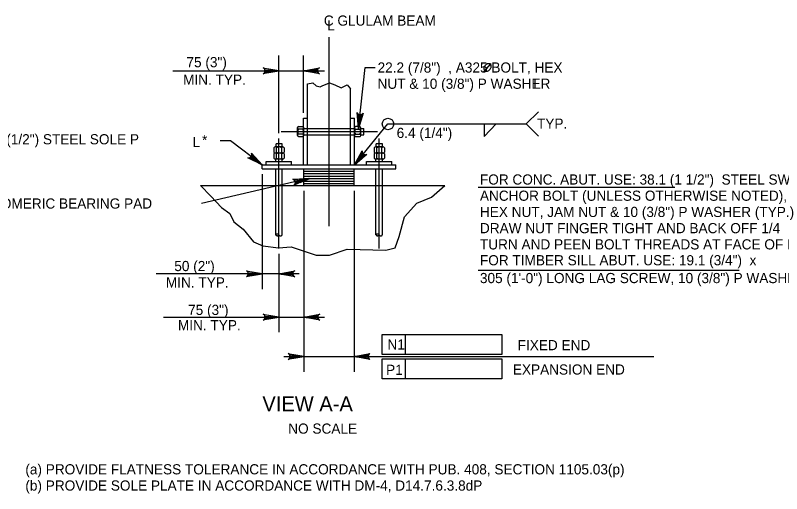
# Model space of a CAD drawing. Extents: x 638263 to 640360, y 293683 to 298655.
# Drawn here: x 638721.5 to 638947.3, y 293868.3 to 294009.4 of the extents above; entities that cross this region are included whole.
import ezdxf

# ---------------------------------------------------------------- set-up
doc = ezdxf.new("R2010")
doc.units = 0
doc.layers.add('3', color=7, linetype='Continuous')
doc.layers.add('4', color=7, linetype='Continuous')

msp = doc.modelspace()

# ---------------------------------------------------------------- linework, layer by layer
at = {"layer": '3'}
for p, q in [((638813.97, 293947.17), (638813.97, 294002.92)), ((638807.64, 293965.26), (638807.64, 293989.18)), ((638820.3, 293965.26), (638820.3, 293987.65)), ((638806.46, 293979.04), (638807.64, 293979.04)), ((638806.46, 293965.26), (638806.46, 293979.04)), ((638820.3, 293979.04), (638821.48, 293979.04)), ((638821.48, 293965.26), (638821.48, 293979.04)), ((638804.96, 293976.61), (638806.25, 293976.61)), ((638823.04, 293976.57), (638821.75, 293976.57)), ((638799.85, 293975.1), (638828.29, 293975.1)), ((638804.69, 293973.97), (638804.7, 293976.24)), ((638806.24, 293974.33), (638804.95, 293974.34)), ((638806.25, 293975.83), (638804.96, 293975.84)), ((638806.5, 293973.96), (638806.51, 293976.23)), ((638806.51, 293976.03), (638821.48, 293976.03)), ((638806.51, 293974.16), (638821.48, 293974.16)), ((638821.48, 293973.92), (638821.48, 293976.2)), ((638821.74, 293974.29), (638823.03, 293974.29)), ((638821.75, 293975.79), (638823.03, 293975.79)), ((638823.3, 293973.92), (638823.3, 293976.19)), ((638823.3, 293975.96), (638824.2, 293975.96)), ((638823.3, 293974.12), (638824.2, 293974.12)), ((638824.2, 293974.12), (638824.2, 293975.96)), ((638799.21, 293940.6), (638799.21, 293973.03)), ((638804.95, 293973.62), (638806.24, 293973.61)), ((638823.03, 293973.57), (638821.74, 293973.57)), ((638828.74, 293940.6), (638828.74, 293973.03)), ((638797.75, 293970.32), (638797.74, 293969.03)), ((638800.4, 293970.58), (638798.12, 293970.58)), ((638800.2, 293971.48), (638798.35, 293971.49)), ((638798.35, 293970.58), (638798.35, 293971.49)), ((638798.52, 293969.03), (638798.52, 293970.32)), ((638800.02, 293969.03), (638800.02, 293970.31)), ((638800.2, 293970.58), (638800.2, 293971.48)), ((638800.75, 293970.31), (638800.74, 293969.03)), ((638827.28, 293970.32), (638827.27, 293969.03)), ((638829.93, 293970.58), (638827.65, 293970.58)), ((638829.73, 293971.48), (638827.88, 293971.49)), ((638827.88, 293970.58), (638827.88, 293971.49)), ((638828.05, 293969.03), (638828.05, 293970.32)), ((638829.55, 293969.03), (638829.55, 293970.31)), ((638829.72, 293970.58), (638829.73, 293971.48)), ((638830.27, 293970.31), (638830.27, 293969.03)), ((638797.74, 293968.5), (638797.74, 293967.22)), ((638800.39, 293968.76), (638798.12, 293968.77)), ((638798.52, 293967.22), (638798.52, 293968.5)), ((638800.02, 293967.21), (638800.02, 293968.5)), ((638800.74, 293968.5), (638800.74, 293967.21)), ((638827.27, 293968.5), (638827.27, 293967.22)), ((638829.92, 293968.76), (638827.65, 293968.77)), ((638828.04, 293967.22), (638828.05, 293968.5)), ((638829.54, 293967.21), (638829.55, 293968.5)), ((638830.27, 293968.5), (638830.27, 293967.21)), ((638794.29, 293964.08), (638794.29, 293965.26)), ((638794.29, 293965.26), (638833.66, 293965.26)), ((638795.47, 293965.26), (638795.47, 293966.24)), ((638795.47, 293966.24), (638802.95, 293966.24)), ((638800.39, 293966.95), (638798.11, 293966.95)), ((638798.28, 293966.24), (638798.28, 293966.95)), ((638800.15, 293966.24), (638800.15, 293966.95)), ((638802.95, 293965.26), (638802.95, 293966.24)), ((638824.99, 293966.24), (638832.48, 293966.24)), ((638824.99, 293965.26), (638824.99, 293966.24)), ((638829.92, 293966.95), (638827.64, 293966.95)), ((638827.81, 293966.24), (638827.81, 293966.95)), ((638829.68, 293966.24), (638829.68, 293966.95)), ((638832.48, 293965.26), (638832.48, 293966.24)), ((638833.66, 293964.08), (638833.66, 293965.26)), ((638794.29, 293964.08), (638833.66, 293964.08)), ((638798.28, 293959.16), (638798.28, 293964.08)), ((638800.15, 293959.16), (638800.15, 293964.08)), ((638806.59, 293959.16), (638806.59, 293964.08)), ((638806.59, 293963.44), (638813.97, 293963.44)), ((638813.97, 293963.44), (638821.35, 293963.44)), ((638821.35, 293959.16), (638821.35, 293964.08)), ((638827.81, 293959.16), (638827.81, 293964.08)), ((638829.68, 293959.16), (638829.68, 293964.08)), ((638806.59, 293962.71), (638813.97, 293962.71)), ((638806.59, 293961.97), (638813.97, 293961.97)), ((638806.59, 293961.23), (638813.97, 293961.23)), ((638813.97, 293962.71), (638821.35, 293962.71)), ((638813.97, 293961.97), (638821.35, 293961.97)), ((638813.97, 293961.23), (638821.35, 293961.23)), ((638776.13, 293959.16), (638848.14, 293959.16)), ((638798.28, 293944.63), (638798.28, 293959.16)), ((638800.15, 293944.63), (638800.15, 293959.16)), ((638806.59, 293960.49), (638813.97, 293960.49)), ((638806.59, 293959.76), (638813.97, 293959.76)), ((638813.97, 293960.49), (638821.35, 293960.49)), ((638813.97, 293959.76), (638821.35, 293959.76)), ((638827.81, 293944.63), (638827.81, 293959.16)), ((638829.68, 293944.63), (638829.68, 293959.16))]:
    msp.add_line(p, q, dxfattribs=at)
for points in [[(638807.64, 293989.18), (638809.22, 293989.48), (638810.14, 293988.56), (638811.37, 293988.26), (638811.98, 293988.56), (638814.13, 293989.48), (638815.66, 293988.87), (638817.5, 293987.95), (638819.33, 293988.87), (638820.3, 293987.65)], [(638794.29, 293965.26), (638790.04, 293967.37), (638790.48, 293967.35), (638790.81, 293967.49), (638791.04, 293967.71), (638791.19, 293967.99), (638791.23, 293968.35), (638791.09, 293968.77), (638794.29, 293965.26), (638791.23, 293968.35), (638791.19, 293967.99), (638794.29, 293965.26), (638791.04, 293967.71), (638790.81, 293967.49), (638794.29, 293965.26), (638790.48, 293967.35)], [(638808.02, 293961.23), (638803.68, 293959.32), (638803.97, 293959.65), (638804.08, 293959.99), (638804.06, 293960.31), (638803.94, 293960.6), (638803.69, 293960.86), (638803.28, 293961.02), (638808.02, 293961.23), (638803.69, 293960.86), (638803.94, 293960.6), (638808.02, 293961.23), (638804.06, 293960.31), (638804.08, 293959.99), (638808.02, 293961.23), (638803.97, 293959.65)], [(638776.13, 293959.16), (638779.19, 293956.09), (638782.25, 293952.72), (638784.71, 293950.89), (638785.93, 293948.44), (638788.69, 293946.29), (638791.75, 293942.62), (638794.51, 293941.39), (638799.11, 293940.78), (638802.79, 293941.08), (638810.14, 293938.63), (638814.13, 293938.63), (638819.33, 293940.47), (638830.67, 293940.17), (638833.43, 293940.78), (638834.66, 293944.15), (638836.19, 293949.97), (638839.87, 293953.95), (638844.16, 293955.79), (638848.14, 293959.16)]]:
    msp.add_lwpolyline(points, dxfattribs=at)
for centre, radius, start, end in [((638805.11, 293976.23), 0.417, 111.1104, 181.6506), ((638806.1, 293976.22), 0.417, 357.9964, 68.5366), ((638821.9, 293976.18), 0.417, 111.1685, 181.7086), ((638822.88, 293976.18), 0.417, 358.0545, 68.5946), ((638805.89, 293975.09), 1.19, 140.8735, 218.7735), ((638805.07, 293973.98), 0.379, 107.2753, 252.3717), ((638805.11, 293976.23), 0.417, 181.6506, 248.5366), ((638805.32, 293975.09), 1.19, 320.8735, 38.7735), ((638806.13, 293973.98), 0.379, 287.2753, 72.3717), ((638806.1, 293976.22), 0.417, 291.1104, 357.9964), ((638821.9, 293976.18), 0.417, 181.7086, 248.5946), ((638822.67, 293975.04), 1.19, 140.9315, 218.8315), ((638821.86, 293973.93), 0.379, 107.3333, 252.4297), ((638822.88, 293976.18), 0.417, 291.1685, 358.0545), ((638822.11, 293975.04), 1.19, 320.9315, 38.8315), ((638822.92, 293973.93), 0.379, 287.3333, 72.4297), ((638798.14, 293970.17), 0.417, 88.0545, 158.5946), ((638798.14, 293970.17), 0.417, 21.1685, 88.0545), ((638799.27, 293969.39), 1.19, 50.9315, 128.8315), ((638800.38, 293970.2), 0.379, 17.3333, 162.4297), ((638827.66, 293970.17), 0.417, 88.0545, 158.5946), ((638827.66, 293970.17), 0.417, 21.1685, 88.0545), ((638828.8, 293969.39), 1.19, 50.9315, 128.8315), ((638829.91, 293970.2), 0.379, 17.3333, 162.4297), ((638798.13, 293969.19), 0.417, 201.1685, 271.7086), ((638798.13, 293968.35), 0.417, 88.0545, 158.5946), ((638798.13, 293968.35), 0.417, 21.1685, 88.0545), ((638799.27, 293969.96), 1.19, 230.9315, 308.8315), ((638799.27, 293967.57), 1.19, 50.9315, 128.8315), ((638800.38, 293969.14), 0.379, 197.3333, 342.4297), ((638800.38, 293968.39), 0.379, 17.3333, 162.4297), ((638827.66, 293969.19), 0.417, 201.1685, 271.7086), ((638827.66, 293968.35), 0.417, 88.0545, 158.5946), ((638827.66, 293969.19), 0.417, 271.7086, 338.5946), ((638827.66, 293968.35), 0.417, 21.1685, 88.0545), ((638828.8, 293969.96), 1.19, 230.9315, 308.8315), ((638828.8, 293967.57), 1.19, 50.9315, 128.8315), ((638829.91, 293969.14), 0.379, 197.3333, 342.4297), ((638829.91, 293968.39), 0.379, 17.3333, 162.4297), ((638798.13, 293967.37), 0.417, 201.1685, 271.7086), ((638798.13, 293967.37), 0.417, 271.7086, 338.5946), ((638799.27, 293968.14), 1.19, 230.9315, 308.8315), ((638800.38, 293967.33), 0.379, 197.3333, 342.4297), ((638827.66, 293967.37), 0.417, 201.1685, 271.7086), ((638827.66, 293967.37), 0.417, 271.7086, 338.5946), ((638828.8, 293968.14), 1.19, 230.9315, 308.8315), ((638829.91, 293967.33), 0.379, 197.3333, 342.4297), ((638798.58, 293944.51), 0.333, 117.9903, 142.0693), ((638798.68, 293944.32), 0.552, 102.4157, 117.9903), ((638798.75, 293944.01), 0.867, 90, 102.4157), ((638798.75, 293944.01), 0.867, 77.5843, 90), ((638798.81, 293944.32), 0.552, 62.0097, 77.5843), ((638798.92, 293944.51), 0.333, 37.9307, 62.0097), ((638828.1, 293944.51), 0.333, 117.9903, 142.0693), ((638828.21, 293944.32), 0.552, 102.4157, 117.9903), ((638828.27, 293944.01), 0.867, 90, 102.4157), ((638828.27, 293944.01), 0.867, 77.5843, 90), ((638828.34, 293944.32), 0.552, 62.0097, 77.5843), ((638828.44, 293944.51), 0.333, 37.9307, 62.0097), ((638798.42, 293944.63), 0.137, 142.0693, 180), ((638798.42, 293944.63), 0.137, 180, 217.9307), ((638798.58, 293944.75), 0.333, 217.9307, 242.0097), ((638798.68, 293944.95), 0.552, 242.0097, 257.5843), ((638798.75, 293945.25), 0.867, 257.5843, 270), ((638798.75, 293945.25), 0.867, 270, 282.4157), ((638798.81, 293944.95), 0.552, 282.4157, 297.9903), ((638798.92, 293944.75), 0.333, 297.9903, 322.0693), ((638799.07, 293944.63), 0.137, 0, 37.9307), ((638799.07, 293944.63), 0.137, 322.0693, 0), ((638799.35, 293944.62), 0.137, 180, 217.9307), ((638799.5, 293944.74), 0.333, 217.9307, 242.0097), ((638799.6, 293944.94), 0.552, 242.0097, 257.5843), ((638799.67, 293945.24), 0.867, 257.5843, 270), ((638799.67, 293945.24), 0.867, 270, 282.4157), ((638799.74, 293944.94), 0.552, 282.4157, 297.9903), ((638799.84, 293944.74), 0.333, 297.9903, 322.0693), ((638800, 293944.62), 0.137, 322.0693, 360), ((638800, 293944.62), 0.137, 360, 1.757), ((638827.95, 293944.63), 0.137, 142.0693, 180), ((638827.95, 293944.63), 0.137, 180, 217.9307), ((638828.1, 293944.75), 0.333, 217.9307, 242.0097), ((638828.21, 293944.95), 0.552, 242.0097, 257.5843), ((638828.27, 293945.25), 0.867, 257.5843, 270), ((638828.27, 293945.25), 0.867, 270, 282.4157), ((638828.34, 293944.95), 0.552, 282.4157, 297.9903), ((638828.44, 293944.75), 0.333, 297.9903, 322.0693), ((638828.6, 293944.63), 0.137, 0, 37.9307), ((638828.6, 293944.63), 0.137, 322.0693, 0), ((638828.87, 293944.62), 0.137, 180, 217.9307), ((638829.03, 293944.74), 0.333, 217.9307, 242.0097), ((638829.13, 293944.94), 0.552, 242.0097, 257.5843), ((638829.2, 293945.24), 0.867, 257.5843, 270), ((638829.2, 293945.24), 0.867, 270, 282.4157), ((638829.27, 293944.94), 0.552, 282.4157, 297.9903), ((638829.37, 293944.74), 0.333, 297.9903, 322.0693), ((638829.52, 293944.62), 0.137, 322.0693, 360), ((638829.52, 293944.62), 0.137, 360, 1.757)]:
    msp.add_arc(centre, radius, start, end, dxfattribs=at)
at = {"layer": '4'}
for p, q in [((638799.21, 293974.6), (638799.21, 293997.51)), ((638806.46, 293980.6), (638806.46, 293997.51)), ((638859.54, 293992.69), (638861.78, 293995.14)), ((638767.98, 293993.01), (638812.59, 293993.01)), ((638822.63, 293975.96), (638824.59, 293994.01)), ((638824.59, 293994.01), (638827.59, 293994.01)), ((638872.1, 293977.32), (638875.73, 293980.9)), ((638821.48, 293965.26), (638831.34, 293977.32)), ((638831.34, 293977.32), (638872.1, 293977.32)), ((638859.64, 293977.32), (638859.64, 293973.65)), ((638859.64, 293973.65), (638863.17, 293977.32)), ((638872.1, 293977.32), (638875.73, 293973.74)), ((638784.93, 293972.32), (638781.93, 293972.32)), ((638794.29, 293965.26), (638784.93, 293972.32)), ((638808.02, 293961.23), (638776.43, 293953.88)), ((638794.29, 293962.52), (638794.29, 293928.67)), ((638857.88, 293958.71), (638915.87, 293958.71)), ((638806.59, 293957.59), (638806.59, 293904.28)), ((638821.35, 293957.59), (638821.35, 293904.28)), ((638799.21, 293939.04), (638799.21, 293915.91)), ((638857.88, 293934.25), (638934.83, 293934.25)), ((638805.18, 293933.17), (638763.04, 293933.17)), ((638765.21, 293920.41), (638812.59, 293920.41)), ((638829.62, 293915.3), (638836.47, 293915.3)), ((638829.62, 293909.39), (638829.62, 293915.3)), ((638836.47, 293909.39), (638836.47, 293915.3)), ((638836.47, 293915.3), (638864.93, 293915.3)), ((638864.93, 293915.3), (638864.93, 293909.39)), ((638800.62, 293908.78), (638909.71, 293908.78)), ((638864.93, 293909.39), (638829.62, 293909.39)), ((638829.62, 293908.11), (638836.47, 293908.11)), ((638829.62, 293902.21), (638829.62, 293908.11)), ((638836.47, 293902.21), (638836.47, 293908.11)), ((638836.47, 293908.11), (638864.93, 293908.11)), ((638864.93, 293908.11), (638864.93, 293902.21)), ((638864.93, 293902.21), (638829.62, 293902.21))]:
    msp.add_line(p, q, dxfattribs=at)
for points in [[(638799.21, 293993.01), (638794.55, 293992.14), (638794.91, 293992.39), (638795.09, 293992.7), (638795.15, 293993.01), (638795.09, 293993.32), (638794.91, 293993.64), (638794.55, 293993.88), (638799.21, 293993.01), (638794.91, 293993.64), (638795.09, 293993.32), (638799.21, 293993.01), (638795.15, 293993.01), (638795.09, 293992.7), (638799.21, 293993.01), (638794.91, 293992.39)], [(638806.46, 293993.01), (638811.12, 293993.88), (638810.76, 293993.64), (638810.58, 293993.32), (638810.52, 293993.01), (638810.58, 293992.7), (638810.76, 293992.39), (638811.12, 293992.14), (638806.46, 293993.01), (638810.76, 293992.39), (638810.58, 293992.7), (638806.46, 293993.01), (638810.52, 293993.01), (638810.58, 293993.32), (638806.46, 293993.01), (638810.76, 293993.64)], [(638822.63, 293975.96), (638822.26, 293980.69), (638822.47, 293980.31), (638822.76, 293980.09), (638823.07, 293980), (638823.38, 293980.02), (638823.71, 293980.17), (638824, 293980.5), (638822.63, 293975.96), (638823.71, 293980.17), (638823.38, 293980.02), (638822.63, 293975.96), (638823.07, 293980), (638822.76, 293980.09), (638822.63, 293975.96), (638822.47, 293980.31)], [(638821.48, 293965.26), (638823.76, 293969.42), (638823.72, 293968.99), (638823.85, 293968.64), (638824.05, 293968.41), (638824.33, 293968.25), (638824.69, 293968.19), (638825.11, 293968.32), (638821.48, 293965.26), (638824.69, 293968.19), (638824.33, 293968.25), (638821.48, 293965.26), (638824.05, 293968.41), (638823.85, 293968.64), (638821.48, 293965.26), (638823.72, 293968.99)], [(638794.29, 293933.17), (638789.63, 293932.3), (638789.98, 293932.55), (638790.17, 293932.86), (638790.22, 293933.17), (638790.17, 293933.49), (638789.98, 293933.8), (638789.63, 293934.05), (638794.29, 293933.17), (638789.98, 293933.8), (638790.17, 293933.49), (638794.29, 293933.17), (638790.22, 293933.17), (638790.17, 293932.86), (638794.29, 293933.17), (638789.98, 293932.55)], [(638799.21, 293933.17), (638803.87, 293934.05), (638803.51, 293933.8), (638803.33, 293933.49), (638803.27, 293933.17), (638803.33, 293932.86), (638803.51, 293932.55), (638803.87, 293932.3), (638799.21, 293933.17), (638803.51, 293932.55), (638803.33, 293932.86), (638799.21, 293933.17), (638803.27, 293933.17), (638803.33, 293933.49), (638799.21, 293933.17), (638803.51, 293933.8)], [(638799.21, 293920.41), (638794.55, 293919.54), (638794.91, 293919.78), (638795.09, 293920.1), (638795.15, 293920.41), (638795.09, 293920.72), (638794.91, 293921.03), (638794.55, 293921.28), (638799.21, 293920.41), (638794.91, 293921.03), (638795.09, 293920.72), (638799.21, 293920.41), (638795.15, 293920.41), (638795.09, 293920.1), (638799.21, 293920.41), (638794.91, 293919.78)], [(638806.59, 293920.41), (638811.25, 293921.28), (638810.89, 293921.03), (638810.71, 293920.72), (638810.65, 293920.41), (638810.71, 293920.1), (638810.89, 293919.78), (638811.25, 293919.54), (638806.59, 293920.41), (638810.89, 293919.78), (638810.71, 293920.1), (638806.59, 293920.41), (638810.65, 293920.41), (638810.71, 293920.72), (638806.59, 293920.41), (638810.89, 293921.03)], [(638806.59, 293908.78), (638801.93, 293907.91), (638802.29, 293908.16), (638802.47, 293908.47), (638802.53, 293908.78), (638802.47, 293909.09), (638802.29, 293909.41), (638801.93, 293909.66), (638806.59, 293908.78), (638802.29, 293909.41), (638802.47, 293909.09), (638806.59, 293908.78), (638802.53, 293908.78), (638802.47, 293908.47), (638806.59, 293908.78), (638802.29, 293908.16)], [(638821.35, 293908.78), (638826.01, 293909.66), (638825.65, 293909.41), (638825.47, 293909.09), (638825.42, 293908.78), (638825.47, 293908.47), (638825.65, 293908.16), (638826.01, 293907.91), (638821.35, 293908.78), (638825.65, 293908.16), (638825.47, 293908.47), (638821.35, 293908.78), (638825.42, 293908.78), (638825.47, 293909.09), (638821.35, 293908.78), (638825.65, 293909.41)]]:
    msp.add_lwpolyline(points, dxfattribs=at)
for points in [[(638796.21, 293993.51), (638796.21, 293992.51), (638799.21, 293993.01)], [(638809.46, 293993.51), (638809.46, 293992.51), (638806.46, 293993.01)], [(638822.51, 293979.51), (638823.5, 293979.41), (638822.68, 293976.48)], [(638792.19, 293967.46), (638791.59, 293966.67), (638794.29, 293965.26)], [(638823.77, 293967.27), (638822.99, 293967.9), (638821.48, 293965.26)], [(638805.25, 293961.1), (638805.48, 293960.12), (638808.28, 293961.29)], [(638791.29, 293933.67), (638791.29, 293932.67), (638794.29, 293933.17)], [(638802.21, 293933.67), (638802.21, 293932.67), (638799.21, 293933.17)], [(638796.21, 293920.91), (638796.21, 293919.91), (638799.21, 293920.41)], [(638809.59, 293920.91), (638809.59, 293919.91), (638806.59, 293920.41)], [(638803.59, 293909.28), (638803.59, 293908.28), (638806.59, 293908.78)], [(638824.35, 293909.28), (638824.35, 293908.28), (638821.35, 293908.78)]]:
    msp.add_lwpolyline(points, close=True, dxfattribs=at)
msp.add_circle((638831.34, 293977.32), 1.69, dxfattribs=at)
msp.add_arc((638799.35, 293944.63), 0.137, 180, 182.0078, dxfattribs=at)
msp.add_spline([(638861.54, 293994.9), (638861.37, 293995.03), (638861.19, 293995.08), (638860.98, 293995.1), (638860.85, 293995.1), (638860.63, 293995.05), (638860.43, 293994.96), (638860.3, 293994.88), (638860.03, 293994.67), (638859.83, 293994.4), (638859.7, 293994.15), (638859.63, 293993.92), (638859.6, 293993.7), (638859.63, 293993.52), (638859.72, 293993.26), (638859.82, 293993.12), (638860, 293992.97), (638860.29, 293992.9), (638860.63, 293992.91), (638861.04, 293993.11), (638861.35, 293993.37), (638861.58, 293993.68), (638861.73, 293994.02), (638861.78, 293994.38), (638861.71, 293994.62), (638861.55, 293994.9)], degree=3, dxfattribs=at)

# ---------------------------------------------------------------- texts
for s, height, p in [('C GLULAM BEAM', 3, (638812.44, 294006.31)), ('L', 3, (638813.42, 294004.9)), ('75 (3")', 3, (638771.96, 293994.05)), ('22.2 (7/8")  , A325 BOLT, HEX', 3, (638828.27, 293992.47)), ('MIN. TYP.', 3, (638770.97, 293988.87)), ('NUT & 10 (3/8") P WASHER', 3, (638828.27, 293987.69)), ('L', 3, (638874.17, 293987.69)), ('TYP.', 3, (638875.25, 293975.92)), ('6.4 (1/4")', 3, (638833.9, 293973.19)), ('12 (1/2") STEEL SOLE P', 3, (638713.3, 293971.32)), ('L', 3, (638773.75, 293970.51)), ('*', 3, (638776.55, 293971.07)), ('FOR CONC. ABUT. USE: 38.1 (1 1/2")  STEEL SWEDGE', 3, (638858.43, 293959.46)), ('ANCHOR BOLT (UNLESS OTHERWISE NOTED), ', 3, (638858.43, 293954.68)), ('ELASTOMERIC BEARING PAD', 3, (638704.55, 293952.38)), ('HEX NUT, JAM NUT & 10 (3/8") P WASHER (TYP.)', 3, (638858.43, 293949.9)), ('DRAW NUT FINGER TIGHT AND BACK OFF 1/4', 3, (638858.43, 293945.12)), ('TURN AND PEEN BOLT THREADS AT FACE OF NUTS.', 3, (638858.43, 293940.34)), ('FOR TIMBER SILL ABUT. USE: 19.1 (3/4")  x ', 3, (638858.43, 293935.66)), ('50 (2")', 3, (638768.38, 293933.95)), ('305 (1\'-0") LONG LAG SCREW, 10 (3/8") P WASHER', 3, (638858.43, 293930.41)), ('MIN. TYP.', 3, (638765.9, 293929.12)), ('75 (3")', 3, (638772.45, 293921.02)), ('MIN. TYP.', 3, (638769.45, 293916.52)), ('N1', 3, (638831.18, 293910.82)), ('FIXED END', 3, (638869.55, 293910.63)), ('P1', 3, (638830.79, 293903.36)), ('EXPANSION END', 3, (638868.14, 293903.45)), ('VIEW A-A', 4.429, (638794.33, 293892.63)), ('NO SCALE', 3, (638801.95, 293886.03)), ('(a) PROVIDE FLATNESS TOLERANCE IN ACCORDANCE WITH PUB. 408, SECTION 1105.03(p)', 3, (638724.49, 293874.03)), ('(b) PROVIDE SOLE PLATE IN ACCORDANCE WITH DM-4, D14.7.6.3.8dP', 3, (638724.49, 293869.25))]:
    msp.add_text(s, height=height, dxfattribs=at).set_placement(p)

doc.saveas('drawing.dxf')
